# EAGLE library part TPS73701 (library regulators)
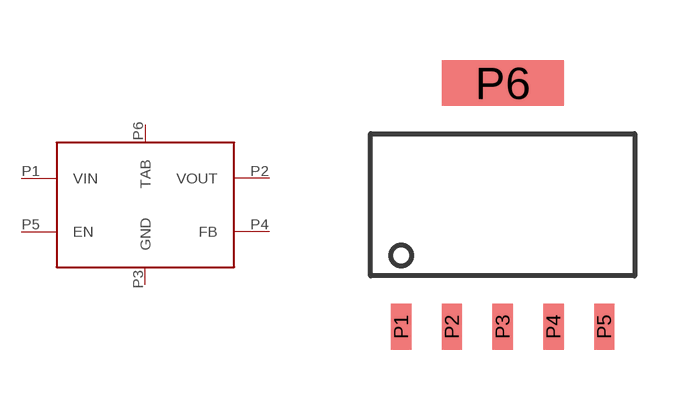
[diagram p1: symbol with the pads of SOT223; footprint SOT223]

Designator prefix -

## TPS73701  [SOT223]
P1  VIN
P2  VOUT
P3  GND
P4  FB
P5  EN
P6  TAB

## Footprint SOT223 (pad centres in mm)
smd 0.508 x 1.143: P1 -2.54,-3.048; P2 -1.27,-3.048; P3 0,-3.048; P4 1.27,-3.048; P5 2.54,-3.048
smd 3.048 x 1.143: P6 0,3.048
